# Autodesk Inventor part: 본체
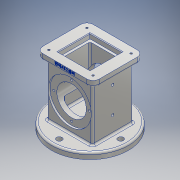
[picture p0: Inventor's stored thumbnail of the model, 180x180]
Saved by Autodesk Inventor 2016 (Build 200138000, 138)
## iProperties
Created: 2018-10
Part Number: 본체
Material: 알루미늄 6061
Document SubType Name: Modeling
Designer: USER
Mass: 984.558 g
Surface Area: 743.902 cm^2
Volume: 364.651 cm^3
Density: 2.7 g/cm^3
Appearance: 알루미늄 - 평지
Author: USER
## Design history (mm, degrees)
sketch "스케치1"
  geometry: C1 r 62.5 at (0, 0); 1 further point
  constraints: 1 centre point, 1 coincident
  dimensions: "d0" = 125 diameter of C1
extrude "돌출1" new body sketch "스케치1" distance "d1" = 10; taper "d2" = 0 deg
node "작업 평면1"
sketch "스케치2"
  geometry: L1 (-36, 41)-(36, 41); L2 (46, 31)-(46, -31); L3 (36, -41)-(-36, -41); L4 (-46, -31)-(-46, 31); A1 r 10 centre (-36, 31) between (-36, 41) and (-46, 31); A2 r 10 centre (-36, -31) between (-46, -31) and (-36, -41); A3 r 10 centre (36, -31) between (36, -41) and (46, -31); A4 r 10 centre (36, 31) between (46, 31) and (36, 41); 6 further points
  constraints: 8 end point, 8 point on circle, 8 tangent, 6 point on line, 4 centre point, 3 equal radius, 2 midpoint, 2 parallel, 1 horizontal, 1 horizontal alignment, 1 perpendicular, 1 vertical alignment
  dimensions: "d4" = 92 distance of point (-46, 41) point (46, 41); "d5" = 82 distance of point (46, 41) point (46, -41); "d6" = 10 radius of A1
extrude "돌출2" join sketch "스케치2" distance "d7" = 10; taper "d8" = 0 deg
sketch "스케치3"
  geometry: L1 (37, -33)-(-37, -33); L2 (-37, -33)-(-37, 33); L3 (-37, 33)-(37, 33); L4 (37, 33)-(37, -33); 3 further points
  constraints: 8 end point, 2 midpoint, 2 parallel, 1 horizontal, 1 horizontal alignment, 1 perpendicular, 1 vertical alignment
  dimensions: "d9" = 74 distance of L1.start L1.end; "d10" = 66 distance of L1.end L2.end
extrude "돌출3" join sketch "스케치3" stored distance "d11" = 88; taper "d12" = 0 deg
sketch "스케치4"
  geometry: L1 (-33, 54)-(33, 54); L2 (-62.5, 0)-(62.5, 0) reference; L3 (-33, 89)-(-30, 89); L4 (-30, 89)-(-30, 78); L5 (-30, 78)-(30, 78); L6 (30, 78)-(30, 89); L7 (30, 89)-(33, 89); L8 (33, 98)-(33, 10) reference; L9 (-33, 89)-(-33, 54); L10 (-33, 98)-(-33, 10) reference; L11 (33, 89)-(33, 54); 2 further points
  constraints: 16 end point, 3 perpendicular, 3 point on line, 2 horizontal, 2 vertical alignment, 1 collinear, 1 midpoint
  dimensions: "d13" = 66 distance of L1.start L1.end; "d14" = 54 distance between parallel lines of L2 L1; "d15" = 70 diameter of L7 L1; "d16" = 48 diameter of L5 L1; "d17" = 3 distance of L6.end L7.end; "d18" = 3 distance of L3.start L3.end
revolve "회전1" sketch "스케치4" stored, may be unused: angle "d19" = 90 deg
sketch "스케치5"
  geometry: L1 (-26, -26)-(26, -26); L2 (26, -26)-(26, 26); L3 (26, 26)-(-26, 26); L4 (-26, 26)-(-26, -26); 3 further points
  constraints: 8 end point, 2 midpoint, 2 parallel, 1 horizontal, 1 horizontal alignment, 1 perpendicular, 1 vertical alignment
  dimensions: "d20" = 52 distance of L3.end L1.start; "d21" = 52 distance of L2.end L3.end
extrude "돌출4" cut sketch "스케치5" distance "d22" = 8; taper "d23" = 0 deg
sketch "스케치6"
  geometry: L1 (-22, -22)-(22, -22); L2 (22, -22)-(22, 22); L3 (22, 22)-(-22, 22); L4 (-22, 22)-(-22, -22); 3 further points
  constraints: 8 end point, 2 midpoint, 2 parallel, 1 horizontal, 1 horizontal alignment, 1 perpendicular, 1 vertical alignment
  dimensions: "d24" = 44 distance of L3.end L1.start; "d25" = 44 distance of L2.end L3.end
extrude "돌출5" cut sketch "스케치6" distance "d26" = 74; taper "d27" = 0 deg
sketch "스케치7"
  geometry: C1 r 28 at (0, 0); 1 further point
  constraints: 1 centre point, 1 coincident
  dimensions: "d28" = 56 diameter of C1
extrude "돌출6" cut sketch "스케치7" distance "d29" = 18; taper "d30" = -10 deg
sketch "스케치8"
  geometry: C1 r 4.5 at (0, 50); C2 r 4.5 at (-50, 0); C3 r 4.5 at (0, -50); C4 r 4.5 at (50, 0); A1 r 50 centre (0, 0) between (0, 50) and (-50, 0); 1 further point
  constraints: 5 centre point, 4 point on circle, 2 horizontal alignment, 2 vertical alignment, 1 coincident
  dimensions: "d31" = 100 diameter of A1; "d32" = 9 diameter of C1; "d33" = 9 diameter of C2; "d34" = 9 diameter of C3; "d35" = 9 diameter of C4
extrude "돌출7" cut sketch "스케치8" stored distance "d36" = 18; taper "d37" = 0 deg
sketch "스케치9" dims "d38" = 58
  geometry: C1 r 35 at (0, 0) reference; 3 further points
  constraints: 2 vertical alignment, 3 other
hole "구멍1" sketch "스케치9" at (0, 29) diameter "d39" = 3.242; stored, may be unused: countersink angle "d43" = 90 deg, drill point angle "d45" = 118 deg; dims "d40" = 4, "d41" = 4, "d42" = 2, "d44" = 6
sketch "스케치10"
  geometry: L1 (98, 33)-(-10, 33); L2 (-10, 7)-(-10, 59) reference; L3 (98, 61)-(98, 5) reference; 2 further points
  constraints: 2 end point, 2 point on line, 1 midpoint
  dimensions: "d49" = 37 distance from line of L3 point (61, 33); "d50" = 43 distance of point (61, 33) point (18, 33)
hole "구멍2" sketch "스케치10" at (61, 33), (18, 33) diameter "d51" = 4.134; stored, may be unused: countersink angle "d55" = 90 deg, drill point angle "d57" = 118 deg; dims "d52" = 28, "d53" = 4, "d54" = 2, "d56" = 30
sketch "스케치11"
  geometry: L1 (-36, 31)-(36, 31); L2 (36, 31)-(36, -31); L3 (36, -31)-(-36, -31); L4 (-36, -31)-(-36, 31); 7 further points
  constraints: 8 end point, 4 coincident, 2 midpoint, 2 parallel, 1 horizontal, 1 horizontal alignment, 1 perpendicular, 1 vertical alignment
  dimensions: "d58" = 72 distance of L1.start L1.end; "d59" = 62 distance of L1.end L2.end
hole "구멍3" sketch "스케치11" at (-36, 31), (-36, -31), (36, -31), (36, 31) diameter "d60" = 3.242; stored, may be unused: countersink angle "d64" = 90 deg, drill point angle "d66" = 118 deg; dims "d61" = 4, "d62" = 4, "d63" = 2, "d65" = 6
chamfer "모따기1" distance "d67" = 1; stored, may be unused: second distance "d68" = 2, angle "d69" = 45 deg
fillet "모깎기1" dims "d70" = 3
fillet "모깎기2" dims "d71" = 3
fillet "모깎기3" dims "d72" = 3
fillet "모깎기4" dims "d73" = 3
fillet "모깎기5" dims "d74" = 3
fillet "모깎기6" dims "d75" = 3
sketch "스케치12" dims "d24" = 44
  geometry: L1 (-10, 0)-(-10, -7) reference; L2 (72, -7)-(0, -7) reference; 2 further points
  constraints: 1 other
  dimensions: "d76" = 46 distance from line of point (36, -3) L1; "d77" = 4 distance from line of point (36, -3) L2
feature "엠보싱1" sketch "스케치12" dims "d78" = 0.5, "d79" = 0
node "솔리드1"
pattern_circular "원형 패턴1" dims angle "d47" = 360 deg
mirror "대칭1"
other parameters: "d3" = 98
